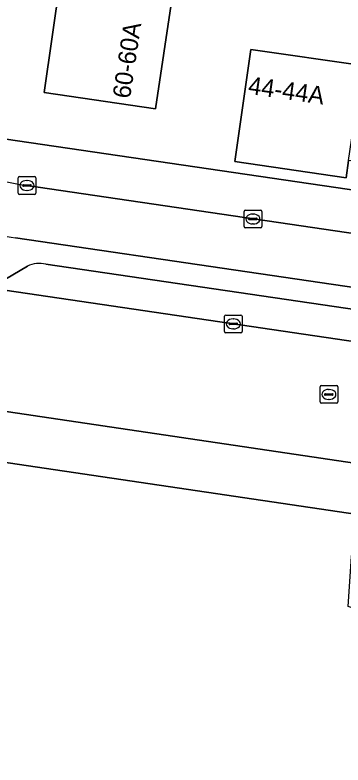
# Model space of a CAD drawing. Extents: x 163683 to 164494, y 382709 to 383872.
# Drawn here: x 163789.21 to 163807.74, y 382929.41 to 382971.74 of the extents above; entities that cross this region are included whole.
import ezdxf

# ---------------------------------------------------------------- set-up
doc = ezdxf.new("R2010")
doc.units = 0
for name, color, linetype in [('IMGEO_Erf', 7, 'Continuous'), ('IMGEO_Fietspad_gesloten', 7, 'Continuous'), ('IMGEO_Kolk', 7, 'Continuous'), ('IMGEO_Pand', 7, 'Continuous'), ('IMGEO_Pand_nummerreeks', 7, 'Continuous'), ('IMGEO_Parkeervlak_open', 7, 'Continuous'), ('IMGEO_Rijbaan_lokaal_gesloten', 7, 'Continuous'), ('IMGEO_Rioolput', 7, 'Continuous'), ('IMGEO_Verkeerseiland_open', 7, 'Continuous'), ('IMGEO_Voetpad_open', 7, 'Continuous')]:
    doc.layers.add(name, color=color, linetype=linetype)

msp = doc.modelspace()

# ---------------------------------------------------------------- linework, layer by layer
at = {"layer": 'IMGEO_Erf'}
for points in [[(163837.364, 382983.156), (163787.22, 382990.507), (163785.123, 382975.744), (163783.566, 382965.481), (163831.088, 382958.518), (163833.909, 382958.105), (163834.128, 382959.773), (163834.947, 382966.01)], [(163797.142, 382966.453), (163790.854, 382967.367), (163791.761, 382973.664), (163790.783, 382973.814), (163791.712, 382980.131), (163791.752, 382980.126), (163792.737, 382979.988), (163793.676, 382986.267), (163799.981, 382985.325), (163799.032, 382979.016), (163798.049, 382979.169), (163797.104, 382972.889), (163798.09, 382972.752)], [(163821.572, 382967.978), (163821.428, 382966.984), (163827.718, 382966.071), (163828.007, 382968.061), (163834.316, 382967.145), (163833.4, 382960.832), (163827.104, 382961.77), (163826.811, 382959.78), (163821.024, 382960.616), (163820.497, 382960.692), (163820.639, 382961.695), (163814.344, 382962.612), (163808.049, 382963.528), (163807.919, 382962.549), (163801.626, 382963.48), (163802.529, 382969.794), (163808.839, 382968.892), (163808.979, 382969.87), (163815.263, 382968.926)]]:
    msp.add_lwpolyline(points, close=True, dxfattribs=at)
msp.add_lwpolyline([(163823.989, 382888.588), (163824.028, 382888.845), (163825.825, 382900.898), (163825.387, 382900.945), (163830.344, 382934.912), (163822.429, 382936.108), (163810.148, 382937.656), (163808.032, 382938.355), (163808.213, 382941.186), (163808.551, 382943.548), (163749.873, 382952.231)], dxfattribs=at)
at = {"layer": 'IMGEO_Fietspad_gesloten'}
for points in [[(163889.537, 382947.425), (163848.504, 382953.484), (163841.466, 382955.031), (163836.819, 382955.733), (163829.321, 382956.326), (163789.89, 382962.121)], [(163789.243, 382959.169), (163828.494, 382953.413), (163832.338, 382953.004), (163834.79, 382952.839), (163842.904, 382951.651), (163844.9, 382951.157), (163848.013, 382950.544), (163885.873, 382944.918), (163888.388, 382944.514)]]:
    msp.add_lwpolyline(points, dxfattribs=at)
for centre, radius, start, end in [((163791.374, 382973.659), 11.633, 247.532, 262.6726), ((163789.978, 382966.144), 7.014, 248.2003, 263.9869)]:
    msp.add_arc(centre, radius, start, end, dxfattribs=at)
at = {"layer": 'IMGEO_Kolk'}
for p, q in [((163789.389, 382961.695), (163789.389, 382962.547)), ((163789.464, 382962.621), (163790.316, 382962.621)), ((163790.39, 382962.547), (163790.39, 382961.695)), ((163789.648, 382962.115), (163789.648, 382962.127)), ((163790.086, 382962.078), (163789.688, 382962.078)), ((163789.691, 382962.164), (163790.089, 382962.164)), ((163789.877, 382962.401), (163789.902, 382962.401)), ((163790.132, 382962.127), (163790.132, 382962.115)), ((163790.316, 382961.621), (163789.464, 382961.621)), ((163789.9, 382961.841), (163789.875, 382961.841)), ((163802.146, 382959.801), (163802.146, 382960.653)), ((163802.221, 382960.727), (163803.073, 382960.727)), ((163802.634, 382960.507), (163802.659, 382960.507)), ((163803.147, 382960.653), (163803.147, 382959.801)), ((163802.405, 382960.221), (163802.405, 382960.233)), ((163802.843, 382960.184), (163802.445, 382960.184)), ((163802.448, 382960.27), (163802.846, 382960.27)), ((163802.657, 382959.947), (163802.632, 382959.947)), ((163802.889, 382960.233), (163802.889, 382960.221)), ((163803.073, 382959.727), (163802.221, 382959.727)), ((163801.037, 382953.883), (163801.037, 382954.735)), ((163801.112, 382954.809), (163801.964, 382954.809)), ((163801.525, 382954.589), (163801.55, 382954.589)), ((163802.038, 382954.735), (163802.038, 382953.883)), ((163801.296, 382954.303), (163801.296, 382954.315)), ((163801.734, 382954.266), (163801.336, 382954.266)), ((163801.339, 382954.352), (163801.737, 382954.352)), ((163801.548, 382954.029), (163801.523, 382954.029)), ((163801.78, 382954.315), (163801.78, 382954.303)), ((163801.964, 382953.809), (163801.112, 382953.809))]:
    msp.add_line(p, q, dxfattribs=at)
for points in [[(163789.389, 382961.695), (163789.389, 382962.547)], [(163789.464, 382962.621), (163790.316, 382962.621)], [(163790.39, 382962.547), (163790.39, 382961.695)], [(163790.316, 382961.621), (163789.464, 382961.621)], [(163802.146, 382959.801), (163802.146, 382960.653)], [(163802.221, 382960.727), (163803.073, 382960.727)], [(163803.147, 382960.653), (163803.147, 382959.801)], [(163803.073, 382959.727), (163802.221, 382959.727)], [(163801.037, 382953.883), (163801.037, 382954.735)], [(163801.112, 382954.809), (163801.964, 382954.809)], [(163802.038, 382954.735), (163802.038, 382953.883)], [(163801.964, 382953.809), (163801.112, 382953.809)]]:
    msp.add_lwpolyline(points, dxfattribs=at)
for centre, radius, start, end in [((163789.466, 382962.545), 0.0765, 91.552, 178.448), ((163789.466, 382962.545), 0.0765, 91.552, 178.448), ((163790.314, 382962.545), 0.0765, 1.552, 88.448), ((163790.314, 382962.545), 0.0765, 1.552, 88.448), ((163789.688, 382962.124), 0.0403, 85.8775, 175.7526), ((163789.685, 382962.114), 0.0366, 178.938, 274.7102), ((163790.089, 382962.121), 0.043, 264.8664, 352.4533), ((163790.093, 382962.126), 0.0386, 1.7309, 96.639), ((163789.466, 382961.697), 0.0765, 181.552, 268.448), ((163789.466, 382961.697), 0.0765, 181.552, 268.448), ((163790.314, 382961.697), 0.0765, 271.552, 358.448), ((163790.314, 382961.697), 0.0765, 271.552, 358.448), ((163802.223, 382960.651), 0.0765, 91.552, 178.448), ((163802.223, 382960.651), 0.0765, 91.552, 178.448), ((163803.071, 382960.651), 0.0765, 1.552, 88.448), ((163803.071, 382960.651), 0.0765, 1.552, 88.448), ((163802.445, 382960.23), 0.0403, 85.8775, 175.7526), ((163802.442, 382960.22), 0.0366, 178.938, 274.7102), ((163802.846, 382960.227), 0.043, 264.8664, 352.4533), ((163802.85, 382960.232), 0.0386, 1.7309, 96.639), ((163802.223, 382959.803), 0.0765, 181.552, 268.448), ((163802.223, 382959.803), 0.0765, 181.552, 268.448), ((163803.071, 382959.803), 0.0765, 271.552, 358.448), ((163803.071, 382959.803), 0.0765, 271.552, 358.448), ((163801.114, 382954.733), 0.0765, 91.552, 178.448), ((163801.114, 382954.733), 0.0765, 91.552, 178.448), ((163801.962, 382954.733), 0.0765, 1.552, 88.448), ((163801.962, 382954.733), 0.0765, 1.552, 88.448), ((163801.336, 382954.312), 0.0403, 85.8775, 175.7526), ((163801.333, 382954.302), 0.0366, 178.938, 274.7102), ((163801.737, 382954.309), 0.043, 264.8664, 352.4533), ((163801.741, 382954.314), 0.0386, 1.7309, 96.639), ((163801.114, 382953.885), 0.0765, 181.552, 268.448), ((163801.114, 382953.885), 0.0765, 181.552, 268.448), ((163801.962, 382953.885), 0.0765, 271.552, 358.448), ((163801.962, 382953.885), 0.0765, 271.552, 358.448)]:
    msp.add_arc(centre, radius, start, end, dxfattribs=at)
for centre, major_axis, ratio, start_param, end_param in [((163789.876, 382962.121), (-0.387, 0.002), 0.722429, 4.712389, 7.853982), ((163789.901, 382962.121), (-0.39, 0.002), 0.717154, 1.570796, 4.712389), ((163802.633, 382960.227), (-0.387, 0.002), 0.722429, 4.712389, 7.853982), ((163802.658, 382960.227), (-0.39, 0.002), 0.717154, 1.570796, 4.712389), ((163801.524, 382954.309), (-0.387, 0.002), 0.722429, 4.712389, 7.853982), ((163801.549, 382954.309), (-0.39, 0.002), 0.717154, 1.570796, 4.712389)]:
    msp.add_ellipse(centre, major_axis=major_axis, ratio=ratio, start_param=start_param, end_param=end_param, dxfattribs=at)
at = {"layer": 'IMGEO_Pand'}
for points in [[(163798.09, 382972.752), (163797.104, 382972.889), (163791.761, 382973.664), (163790.854, 382967.367), (163797.142, 382966.453)], [(163808.839, 382968.892), (163802.529, 382969.794), (163801.626, 382963.48), (163807.919, 382962.549), (163808.049, 382963.528)]]:
    msp.add_lwpolyline(points, close=True, dxfattribs=at)
at = {"layer": 'IMGEO_Parkeervlak_open'}
for points in [[(163789.915, 382957.561), (163788.685, 382956.826)], [(163828.267, 382952.204), (163790.96, 382957.678)], [(163787.471, 382956.38), (163830.808, 382950)], [(163749.873, 382952.231), (163808.551, 382943.548), (163813.906, 382942.764), (163814.345, 382945.562), (163746.439, 382955.62)]]:
    msp.add_lwpolyline(points, dxfattribs=at)
msp.add_arc((163790.596, 382956.206), 1.516, 76.0965, 116.6802, dxfattribs=at)
at = {"layer": 'IMGEO_Rijbaan_lokaal_gesloten'}
for points in [[(163721.918, 382959.161), (163746.267, 382955.645), (163746.439, 382955.62), (163814.345, 382945.562), (163823.903, 382944.146), (163837.413, 382942.146), (163842.566, 382941.383), (163848.912, 382940.443), (163858.966, 382938.954), (163868.32, 382937.568), (163870.569, 382937.235), (163884.955, 382935.095), (163891.024, 382934.192), (163906.594, 382931.876), (163906.556, 382931.624), (163919.071, 382929.775), (163929.575, 382928.223)], [(163891.228, 382941.384), (163889.788, 382941.027), (163889.122, 382941.068), (163844.076, 382948.022), (163843.854, 382948.077), (163830.808, 382950), (163787.471, 382956.38), (163787.208, 382956.418), (163774.479, 382958.332), (163774.341, 382958.287), (163767.78, 382959.348)]]:
    msp.add_lwpolyline(points, dxfattribs=at)
at = {"layer": 'IMGEO_Rioolput'}
for p, q in [((163806.437, 382949.9), (163806.437, 382950.752)), ((163806.512, 382950.826), (163807.364, 382950.826)), ((163806.925, 382950.606), (163806.95, 382950.606)), ((163807.438, 382950.752), (163807.438, 382949.9)), ((163806.696, 382950.32), (163806.696, 382950.332)), ((163807.134, 382950.283), (163806.736, 382950.283)), ((163806.739, 382950.369), (163807.137, 382950.369)), ((163807.18, 382950.332), (163807.18, 382950.32)), ((163807.364, 382949.826), (163806.512, 382949.826)), ((163806.948, 382950.046), (163806.923, 382950.046))]:
    msp.add_line(p, q, dxfattribs=at)
for points in [[(163806.437, 382949.9), (163806.437, 382950.752)], [(163806.512, 382950.826), (163807.364, 382950.826)], [(163807.438, 382950.752), (163807.438, 382949.9)], [(163807.364, 382949.826), (163806.512, 382949.826)]]:
    msp.add_lwpolyline(points, dxfattribs=at)
for centre, radius, start, end in [((163806.514, 382950.75), 0.0765, 91.552, 178.448), ((163806.514, 382950.75), 0.0765, 91.552, 178.448), ((163807.362, 382950.75), 0.0765, 1.552, 88.448), ((163807.362, 382950.75), 0.0765, 1.552, 88.448), ((163806.736, 382950.329), 0.0403, 85.8775, 175.7526), ((163806.733, 382950.319), 0.0366, 178.938, 274.7102), ((163807.137, 382950.326), 0.043, 264.8664, 352.4533), ((163807.141, 382950.331), 0.0386, 1.7309, 96.639), ((163806.514, 382949.902), 0.0765, 181.552, 268.448), ((163806.514, 382949.902), 0.0765, 181.552, 268.448), ((163807.362, 382949.902), 0.0765, 271.552, 358.448), ((163807.362, 382949.902), 0.0765, 271.552, 358.448)]:
    msp.add_arc(centre, radius, start, end, dxfattribs=at)
for centre, major_axis, ratio, start_param, end_param in [((163806.924, 382950.326), (-0.387, 0.002), 0.722429, 4.712389, 7.853982), ((163806.949, 382950.326), (-0.39, 0.002), 0.717154, 1.570796, 4.712389)]:
    msp.add_ellipse(centre, major_axis=major_axis, ratio=ratio, start_param=start_param, end_param=end_param, dxfattribs=at)
at = {"layer": 'IMGEO_Verkeerseiland_open'}
for points in [[(163847.408, 382949.367), (163885.659, 382943.648), (163885.873, 382944.918), (163848.013, 382950.544), (163844.9, 382951.157), (163842.904, 382951.651), (163834.79, 382952.839), (163832.338, 382953.004), (163828.494, 382953.413), (163789.243, 382959.169)], [(163788.685, 382956.826), (163789.915, 382957.561)], [(163790.96, 382957.678), (163828.267, 382952.204)]]:
    msp.add_lwpolyline(points, dxfattribs=at)
for centre, radius, start, end in [((163789.978, 382966.144), 7.014, 248.2003, 263.9869), ((163790.596, 382956.206), 1.516, 76.0965, 116.6802)]:
    msp.add_arc(centre, radius, start, end, dxfattribs=at)
at = {"layer": 'IMGEO_Voetpad_open'}
msp.add_lwpolyline([(163789.89, 382962.121), (163829.321, 382956.326), (163836.819, 382955.733), (163836.958, 382956.606), (163833.909, 382958.105), (163831.088, 382958.518), (163783.566, 382965.481)], dxfattribs=at)
msp.add_arc((163791.374, 382973.659), 11.633, 247.532, 262.6726, dxfattribs=at)

# ---------------------------------------------------------------- texts
at = {"layer": 'IMGEO_Pand_nummerreeks'}
for s, rotation, p in [('60-60A', 81.4402, (163795.706, 382966.989)), ('44-44A', 351.864, (163802.336, 382967.296))]:
    msp.add_text(s, height=1, rotation=rotation, dxfattribs=at).set_placement(p)

doc.saveas('drawing.dxf')
